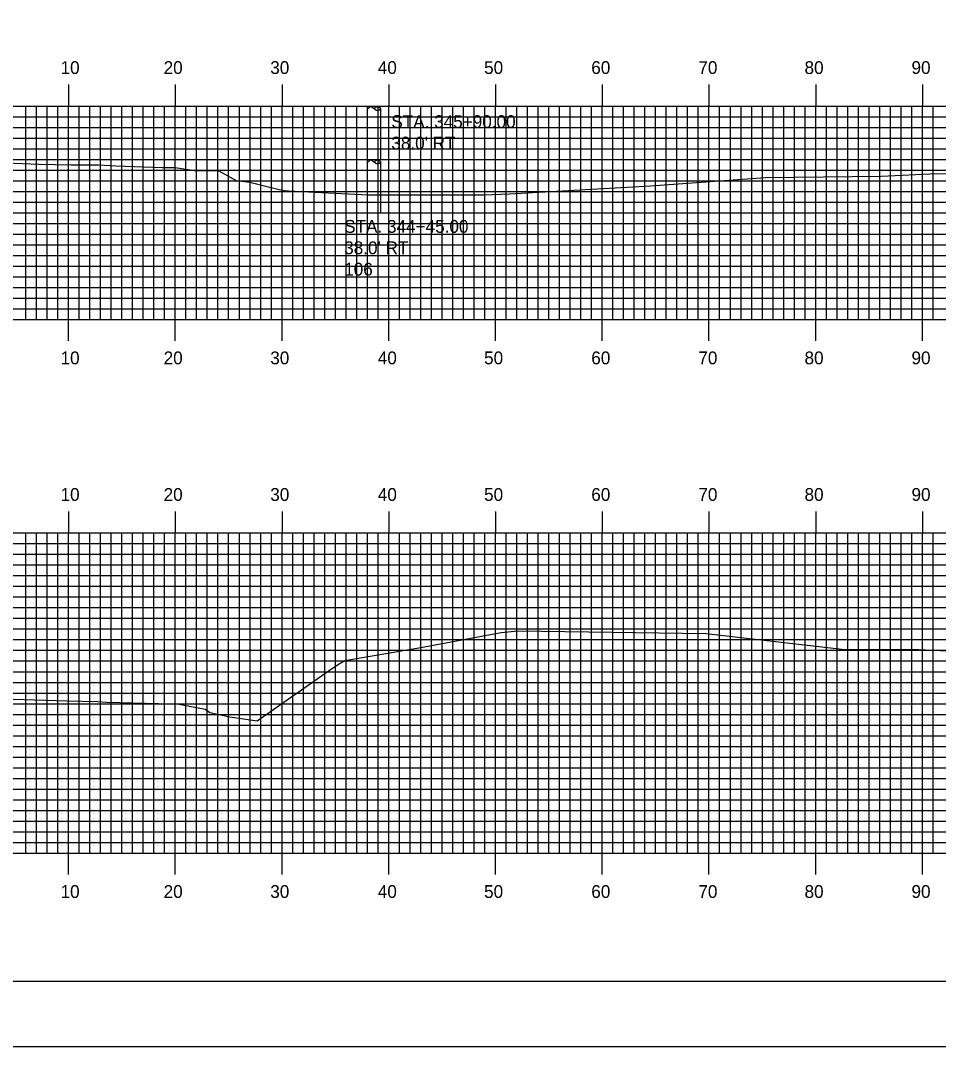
# Model space of a CAD drawing. Extents: x 1825540 to 1825883, y 442591 to 442811.
# Drawn here: x 1825711.4 to 1825797.4, y 442590.5 to 442686.7 of the extents above; entities that cross this region are included whole.
import ezdxf

# ---------------------------------------------------------------- set-up
doc = ezdxf.new("R2010")
doc.units = 0
for name, color, linetype in [('BORDER', 7, 'Continuous'), ('D_Drainage_Text', 7, 'Continuous'), ('D_Utilities_Pole_Joint', 7, 'Continuous'), ('H_V ANNOTATION', 7, 'Continuous'), ('MAJOR', 7, 'Continuous'), ('MINOR', 7, 'Continuous'), ('PLOT BOUNDARY', 7, 'Continuous'), ('S_Roadway_Centerline', 7, 'Continuous')]:
    doc.layers.add(name, color=color, linetype=linetype)

msp = doc.modelspace()

# ---------------------------------------------------------------- linework, layer by layer
at = {"layer": 'BORDER'}
msp.add_lwpolyline([(1825556.274, 442596.665), (1825876.274, 442596.665), (1825876.274, 442806.665), (1825556.274, 442806.665)], close=True, dxfattribs=at)
at = {"layer": 'D_Utilities_Pole_Joint'}
for p, q in [((1825743.874, 442678.423), (1825744.03, 442678.533)), ((1825743.874, 442673.665), (1825743.874, 442678.423)), ((1825744.343, 442678.533), (1825744.499, 442678.423)), ((1825744.655, 442678.533), (1825744.499, 442678.423)), ((1825744.499, 442678.423), (1825744.655, 442678.312)), ((1825745.124, 442678.423), (1825744.968, 442678.533)), ((1825744.968, 442678.312), (1825745.124, 442678.423)), ((1825745.124, 442673.665), (1825745.124, 442678.423)), ((1825743.874, 442673.423), (1825744.03, 442673.533)), ((1825743.874, 442668.665), (1825743.874, 442673.423)), ((1825744.343, 442673.533), (1825744.499, 442673.423)), ((1825744.655, 442673.533), (1825744.499, 442673.423)), ((1825744.499, 442673.423), (1825744.655, 442673.312)), ((1825745.124, 442673.423), (1825744.968, 442673.533)), ((1825744.968, 442673.312), (1825745.124, 442673.423)), ((1825745.124, 442668.665), (1825745.124, 442673.423))]:
    msp.add_line(p, q, dxfattribs=at)
for centre, start, end in [((1825744.187, 442678.312), 90, 125.26439), ((1825744.187, 442678.312), 54.73561, 90), ((1825744.812, 442678.312), 90, 125.26439), ((1825744.812, 442678.533), 234.73561, 270), ((1825744.812, 442678.312), 54.73561, 90), ((1825744.812, 442678.533), 270, 305.26439), ((1825744.187, 442673.312), 90, 125.26439), ((1825744.187, 442673.312), 54.73561, 90), ((1825744.812, 442673.312), 90, 125.26439), ((1825744.812, 442673.312), 54.73561, 90), ((1825744.812, 442673.533), 234.73561, 270), ((1825744.812, 442673.533), 270, 305.26439)]:
    msp.add_arc(centre, 0.271, start, end, dxfattribs=at)
at = {"layer": 'MAJOR'}
for p, q in [((1825715.874, 442680.669), (1825715.874, 442678.665)), ((1825725.874, 442680.669), (1825725.874, 442678.665)), ((1825735.874, 442680.669), (1825735.874, 442678.665)), ((1825745.874, 442680.669), (1825745.874, 442678.665)), ((1825755.874, 442680.669), (1825755.874, 442678.665)), ((1825765.874, 442680.669), (1825765.874, 442678.665)), ((1825775.874, 442680.669), (1825775.874, 442678.665)), ((1825785.874, 442680.669), (1825785.874, 442678.665)), ((1825795.874, 442680.669), (1825795.874, 442678.665)), ((1825565.874, 442678.665), (1825845.874, 442678.665)), ((1825565.874, 442678.665), (1825845.874, 442678.665)), ((1825715.874, 442658.665), (1825715.874, 442678.665)), ((1825725.874, 442658.665), (1825725.874, 442678.665)), ((1825735.874, 442658.665), (1825735.874, 442678.665)), ((1825745.874, 442658.665), (1825745.874, 442678.665)), ((1825755.874, 442658.665), (1825755.874, 442678.665)), ((1825765.874, 442658.665), (1825765.874, 442678.665)), ((1825775.874, 442658.665), (1825775.874, 442678.665)), ((1825785.874, 442658.665), (1825785.874, 442678.665)), ((1825795.874, 442658.665), (1825795.874, 442678.665)), ((1825565.874, 442673.665), (1825845.874, 442673.665)), ((1825565.874, 442668.665), (1825845.874, 442668.665)), ((1825565.874, 442663.665), (1825845.874, 442663.665)), ((1825565.874, 442658.665), (1825845.874, 442658.665)), ((1825565.874, 442658.665), (1825845.874, 442658.665)), ((1825715.874, 442656.661), (1825715.874, 442658.665)), ((1825725.874, 442656.661), (1825725.874, 442658.665)), ((1825735.874, 442656.661), (1825735.874, 442658.665)), ((1825745.874, 442656.661), (1825745.874, 442658.665)), ((1825755.874, 442656.661), (1825755.874, 442658.665)), ((1825765.874, 442656.661), (1825765.874, 442658.665)), ((1825775.874, 442656.661), (1825775.874, 442658.665)), ((1825785.874, 442656.661), (1825785.874, 442658.665)), ((1825795.874, 442656.661), (1825795.874, 442658.665)), ((1825715.874, 442640.669), (1825715.874, 442638.665)), ((1825725.874, 442640.669), (1825725.874, 442638.665)), ((1825735.874, 442640.669), (1825735.874, 442638.665)), ((1825745.874, 442640.669), (1825745.874, 442638.665)), ((1825755.874, 442640.669), (1825755.874, 442638.665)), ((1825765.874, 442640.669), (1825765.874, 442638.665)), ((1825775.874, 442640.669), (1825775.874, 442638.665)), ((1825785.874, 442640.669), (1825785.874, 442638.665)), ((1825795.874, 442640.669), (1825795.874, 442638.665)), ((1825565.874, 442638.665), (1825845.874, 442638.665)), ((1825565.874, 442638.665), (1825845.874, 442638.665)), ((1825715.874, 442608.665), (1825715.874, 442638.665)), ((1825725.874, 442608.665), (1825725.874, 442638.665)), ((1825735.874, 442608.665), (1825735.874, 442638.665)), ((1825745.874, 442608.665), (1825745.874, 442638.665)), ((1825755.874, 442608.665), (1825755.874, 442638.665)), ((1825765.874, 442608.665), (1825765.874, 442638.665)), ((1825775.874, 442608.665), (1825775.874, 442638.665)), ((1825785.874, 442608.665), (1825785.874, 442638.665)), ((1825795.874, 442608.665), (1825795.874, 442638.665)), ((1825565.874, 442633.665), (1825845.874, 442633.665)), ((1825565.874, 442628.665), (1825845.874, 442628.665)), ((1825565.874, 442623.665), (1825845.874, 442623.665)), ((1825565.874, 442618.665), (1825845.874, 442618.665)), ((1825565.874, 442613.665), (1825845.874, 442613.665)), ((1825565.874, 442608.665), (1825845.874, 442608.665)), ((1825565.874, 442608.665), (1825845.874, 442608.665)), ((1825715.874, 442606.661), (1825715.874, 442608.665)), ((1825725.874, 442606.661), (1825725.874, 442608.665)), ((1825735.874, 442606.661), (1825735.874, 442608.665)), ((1825745.874, 442606.661), (1825745.874, 442608.665)), ((1825755.874, 442606.661), (1825755.874, 442608.665)), ((1825765.874, 442606.661), (1825765.874, 442608.665)), ((1825775.874, 442606.661), (1825775.874, 442608.665)), ((1825785.874, 442606.661), (1825785.874, 442608.665)), ((1825795.874, 442606.661), (1825795.874, 442608.665))]:
    msp.add_line(p, q, dxfattribs=at)
at = {"layer": 'MINOR'}
for p, q in [((1825711.874, 442658.665), (1825711.874, 442678.665)), ((1825712.874, 442658.665), (1825712.874, 442678.665)), ((1825713.874, 442658.665), (1825713.874, 442678.665)), ((1825714.874, 442658.665), (1825714.874, 442678.665)), ((1825716.874, 442658.665), (1825716.874, 442678.665)), ((1825717.874, 442658.665), (1825717.874, 442678.665)), ((1825718.874, 442658.665), (1825718.874, 442678.665)), ((1825719.874, 442658.665), (1825719.874, 442678.665)), ((1825720.874, 442658.665), (1825720.874, 442678.665)), ((1825721.874, 442658.665), (1825721.874, 442678.665)), ((1825722.874, 442658.665), (1825722.874, 442678.665)), ((1825723.874, 442658.665), (1825723.874, 442678.665)), ((1825724.874, 442658.665), (1825724.874, 442678.665)), ((1825726.874, 442658.665), (1825726.874, 442678.665)), ((1825727.874, 442658.665), (1825727.874, 442678.665)), ((1825728.874, 442658.665), (1825728.874, 442678.665)), ((1825729.874, 442658.665), (1825729.874, 442678.665)), ((1825730.874, 442658.665), (1825730.874, 442678.665)), ((1825731.874, 442658.665), (1825731.874, 442678.665)), ((1825732.874, 442658.665), (1825732.874, 442678.665)), ((1825733.874, 442658.665), (1825733.874, 442678.665)), ((1825734.874, 442658.665), (1825734.874, 442678.665)), ((1825736.874, 442658.665), (1825736.874, 442678.665)), ((1825737.874, 442658.665), (1825737.874, 442678.665)), ((1825738.874, 442658.665), (1825738.874, 442678.665)), ((1825739.874, 442658.665), (1825739.874, 442678.665)), ((1825740.874, 442658.665), (1825740.874, 442678.665)), ((1825741.874, 442658.665), (1825741.874, 442678.665)), ((1825742.874, 442658.665), (1825742.874, 442678.665)), ((1825743.874, 442658.665), (1825743.874, 442678.665)), ((1825744.874, 442658.665), (1825744.874, 442678.665)), ((1825746.874, 442658.665), (1825746.874, 442678.665)), ((1825747.874, 442658.665), (1825747.874, 442678.665)), ((1825748.874, 442658.665), (1825748.874, 442678.665)), ((1825749.874, 442658.665), (1825749.874, 442678.665)), ((1825750.874, 442658.665), (1825750.874, 442678.665)), ((1825751.874, 442658.665), (1825751.874, 442678.665)), ((1825752.874, 442658.665), (1825752.874, 442678.665)), ((1825753.874, 442658.665), (1825753.874, 442678.665)), ((1825754.874, 442658.665), (1825754.874, 442678.665)), ((1825756.874, 442658.665), (1825756.874, 442678.665)), ((1825757.874, 442658.665), (1825757.874, 442678.665)), ((1825758.874, 442658.665), (1825758.874, 442678.665)), ((1825759.874, 442658.665), (1825759.874, 442678.665)), ((1825760.874, 442658.665), (1825760.874, 442678.665)), ((1825761.874, 442658.665), (1825761.874, 442678.665)), ((1825762.874, 442658.665), (1825762.874, 442678.665)), ((1825763.874, 442658.665), (1825763.874, 442678.665)), ((1825764.874, 442658.665), (1825764.874, 442678.665)), ((1825766.874, 442658.665), (1825766.874, 442678.665)), ((1825767.874, 442658.665), (1825767.874, 442678.665)), ((1825768.874, 442658.665), (1825768.874, 442678.665)), ((1825769.874, 442658.665), (1825769.874, 442678.665)), ((1825770.874, 442658.665), (1825770.874, 442678.665)), ((1825771.874, 442658.665), (1825771.874, 442678.665)), ((1825772.874, 442658.665), (1825772.874, 442678.665)), ((1825773.874, 442658.665), (1825773.874, 442678.665)), ((1825774.874, 442658.665), (1825774.874, 442678.665)), ((1825776.874, 442658.665), (1825776.874, 442678.665)), ((1825777.874, 442658.665), (1825777.874, 442678.665)), ((1825778.874, 442658.665), (1825778.874, 442678.665)), ((1825779.874, 442658.665), (1825779.874, 442678.665)), ((1825780.874, 442658.665), (1825780.874, 442678.665)), ((1825781.874, 442658.665), (1825781.874, 442678.665)), ((1825782.874, 442658.665), (1825782.874, 442678.665)), ((1825783.874, 442658.665), (1825783.874, 442678.665)), ((1825784.874, 442658.665), (1825784.874, 442678.665)), ((1825786.874, 442658.665), (1825786.874, 442678.665)), ((1825787.874, 442658.665), (1825787.874, 442678.665)), ((1825788.874, 442658.665), (1825788.874, 442678.665)), ((1825789.874, 442658.665), (1825789.874, 442678.665)), ((1825790.874, 442658.665), (1825790.874, 442678.665)), ((1825791.874, 442658.665), (1825791.874, 442678.665)), ((1825792.874, 442658.665), (1825792.874, 442678.665)), ((1825793.874, 442658.665), (1825793.874, 442678.665)), ((1825794.874, 442658.665), (1825794.874, 442678.665)), ((1825796.874, 442658.665), (1825796.874, 442678.665)), ((1825565.874, 442677.665), (1825845.874, 442677.665)), ((1825565.874, 442676.665), (1825845.874, 442676.665)), ((1825565.874, 442675.665), (1825845.874, 442675.665)), ((1825565.874, 442674.665), (1825845.874, 442674.665)), ((1825565.874, 442672.665), (1825845.874, 442672.665)), ((1825565.874, 442671.665), (1825845.874, 442671.665)), ((1825565.874, 442670.665), (1825845.874, 442670.665)), ((1825565.874, 442669.665), (1825845.874, 442669.665)), ((1825565.874, 442667.665), (1825845.874, 442667.665)), ((1825565.874, 442666.665), (1825845.874, 442666.665)), ((1825565.874, 442665.665), (1825845.874, 442665.665)), ((1825565.874, 442664.665), (1825845.874, 442664.665)), ((1825565.874, 442662.665), (1825845.874, 442662.665)), ((1825565.874, 442661.665), (1825845.874, 442661.665)), ((1825565.874, 442660.665), (1825845.874, 442660.665)), ((1825565.874, 442659.665), (1825845.874, 442659.665)), ((1825711.874, 442608.665), (1825711.874, 442638.665)), ((1825712.874, 442608.665), (1825712.874, 442638.665)), ((1825713.874, 442608.665), (1825713.874, 442638.665)), ((1825714.874, 442608.665), (1825714.874, 442638.665)), ((1825716.874, 442608.665), (1825716.874, 442638.665)), ((1825717.874, 442608.665), (1825717.874, 442638.665)), ((1825718.874, 442608.665), (1825718.874, 442638.665)), ((1825719.874, 442608.665), (1825719.874, 442638.665)), ((1825720.874, 442608.665), (1825720.874, 442638.665)), ((1825721.874, 442608.665), (1825721.874, 442638.665)), ((1825722.874, 442608.665), (1825722.874, 442638.665)), ((1825723.874, 442608.665), (1825723.874, 442638.665)), ((1825724.874, 442608.665), (1825724.874, 442638.665)), ((1825726.874, 442608.665), (1825726.874, 442638.665)), ((1825727.874, 442608.665), (1825727.874, 442638.665)), ((1825728.874, 442608.665), (1825728.874, 442638.665)), ((1825729.874, 442608.665), (1825729.874, 442638.665)), ((1825730.874, 442608.665), (1825730.874, 442638.665)), ((1825731.874, 442608.665), (1825731.874, 442638.665)), ((1825732.874, 442608.665), (1825732.874, 442638.665)), ((1825733.874, 442608.665), (1825733.874, 442638.665)), ((1825734.874, 442608.665), (1825734.874, 442638.665)), ((1825736.874, 442608.665), (1825736.874, 442638.665)), ((1825737.874, 442608.665), (1825737.874, 442638.665)), ((1825738.874, 442608.665), (1825738.874, 442638.665)), ((1825739.874, 442608.665), (1825739.874, 442638.665)), ((1825740.874, 442608.665), (1825740.874, 442638.665)), ((1825741.874, 442608.665), (1825741.874, 442638.665)), ((1825742.874, 442608.665), (1825742.874, 442638.665)), ((1825743.874, 442608.665), (1825743.874, 442638.665)), ((1825744.874, 442608.665), (1825744.874, 442638.665)), ((1825746.874, 442608.665), (1825746.874, 442638.665)), ((1825747.874, 442608.665), (1825747.874, 442638.665)), ((1825748.874, 442608.665), (1825748.874, 442638.665)), ((1825749.874, 442608.665), (1825749.874, 442638.665)), ((1825750.874, 442608.665), (1825750.874, 442638.665)), ((1825751.874, 442608.665), (1825751.874, 442638.665)), ((1825752.874, 442608.665), (1825752.874, 442638.665)), ((1825753.874, 442608.665), (1825753.874, 442638.665)), ((1825754.874, 442608.665), (1825754.874, 442638.665)), ((1825756.874, 442608.665), (1825756.874, 442638.665)), ((1825757.874, 442608.665), (1825757.874, 442638.665)), ((1825758.874, 442608.665), (1825758.874, 442638.665)), ((1825759.874, 442608.665), (1825759.874, 442638.665)), ((1825760.874, 442608.665), (1825760.874, 442638.665)), ((1825761.874, 442608.665), (1825761.874, 442638.665)), ((1825762.874, 442608.665), (1825762.874, 442638.665)), ((1825763.874, 442608.665), (1825763.874, 442638.665)), ((1825764.874, 442608.665), (1825764.874, 442638.665)), ((1825766.874, 442608.665), (1825766.874, 442638.665)), ((1825767.874, 442608.665), (1825767.874, 442638.665)), ((1825768.874, 442608.665), (1825768.874, 442638.665)), ((1825769.874, 442608.665), (1825769.874, 442638.665)), ((1825770.874, 442608.665), (1825770.874, 442638.665)), ((1825771.874, 442608.665), (1825771.874, 442638.665)), ((1825772.874, 442608.665), (1825772.874, 442638.665)), ((1825773.874, 442608.665), (1825773.874, 442638.665)), ((1825774.874, 442608.665), (1825774.874, 442638.665)), ((1825776.874, 442608.665), (1825776.874, 442638.665)), ((1825777.874, 442608.665), (1825777.874, 442638.665)), ((1825778.874, 442608.665), (1825778.874, 442638.665)), ((1825779.874, 442608.665), (1825779.874, 442638.665)), ((1825780.874, 442608.665), (1825780.874, 442638.665)), ((1825781.874, 442608.665), (1825781.874, 442638.665)), ((1825782.874, 442608.665), (1825782.874, 442638.665)), ((1825783.874, 442608.665), (1825783.874, 442638.665)), ((1825784.874, 442608.665), (1825784.874, 442638.665)), ((1825786.874, 442608.665), (1825786.874, 442638.665)), ((1825787.874, 442608.665), (1825787.874, 442638.665)), ((1825788.874, 442608.665), (1825788.874, 442638.665)), ((1825789.874, 442608.665), (1825789.874, 442638.665)), ((1825790.874, 442608.665), (1825790.874, 442638.665)), ((1825791.874, 442608.665), (1825791.874, 442638.665)), ((1825792.874, 442608.665), (1825792.874, 442638.665)), ((1825793.874, 442608.665), (1825793.874, 442638.665)), ((1825794.874, 442608.665), (1825794.874, 442638.665)), ((1825796.874, 442608.665), (1825796.874, 442638.665)), ((1825565.874, 442637.665), (1825845.874, 442637.665)), ((1825565.874, 442636.665), (1825845.874, 442636.665)), ((1825565.874, 442635.665), (1825845.874, 442635.665)), ((1825565.874, 442634.665), (1825845.874, 442634.665)), ((1825565.874, 442632.665), (1825845.874, 442632.665)), ((1825565.874, 442631.665), (1825845.874, 442631.665)), ((1825565.874, 442630.665), (1825845.874, 442630.665)), ((1825565.874, 442629.665), (1825845.874, 442629.665)), ((1825565.874, 442627.665), (1825845.874, 442627.665)), ((1825565.874, 442626.665), (1825845.874, 442626.665)), ((1825565.874, 442625.665), (1825845.874, 442625.665)), ((1825565.874, 442624.665), (1825845.874, 442624.665)), ((1825565.874, 442622.665), (1825845.874, 442622.665)), ((1825565.874, 442621.665), (1825845.874, 442621.665)), ((1825565.874, 442620.665), (1825845.874, 442620.665)), ((1825565.874, 442619.665), (1825845.874, 442619.665)), ((1825565.874, 442617.665), (1825845.874, 442617.665)), ((1825565.874, 442616.665), (1825845.874, 442616.665)), ((1825565.874, 442615.665), (1825845.874, 442615.665)), ((1825565.874, 442614.665), (1825845.874, 442614.665)), ((1825565.874, 442612.665), (1825845.874, 442612.665)), ((1825565.874, 442611.665), (1825845.874, 442611.665)), ((1825565.874, 442610.665), (1825845.874, 442610.665)), ((1825565.874, 442609.665), (1825845.874, 442609.665))]:
    msp.add_line(p, q, dxfattribs=at)
at = {"layer": 'PLOT BOUNDARY'}
msp.add_lwpolyline([(1825540.087, 442590.547), (1825880.087, 442590.547), (1825880.087, 442810.547), (1825540.087, 442810.547)], close=True, dxfattribs=at)
msp.add_lwpolyline([(1825540.087, 442590.547), (1825880.087, 442590.547), (1825880.087, 442810.547), (1825540.087, 442810.547)], close=True, dxfattribs=at)
at = {"layer": 'S_Roadway_Centerline'}
for points in [[(1825709.987, 442673.349), (1825713.123, 442673.21), (1825716.119, 442673.149), (1825718.687, 442673.155), (1825720.317, 442673.05), (1825724.647, 442672.903), (1825725.865, 442672.912), (1825727.687, 442672.622), (1825729.959, 442672.593), (1825731.582, 442671.681), (1825732.845, 442671.52), (1825735.619, 442670.844), (1825735.959, 442670.771), (1825736.297, 442670.708), (1825736.475, 442670.709), (1825743.935, 442670.35), (1825754.427, 442670.341), (1825754.763, 442670.342), (1825757.2, 442670.449), (1825770.379, 442671.174), (1825781.156, 442671.959), (1825791.996, 442672.081), (1825797.221, 442672.353), (1825800.871, 442672.29)], [(1825706.637, 442623.226), (1825715.7, 442622.926), (1825718.565, 442622.868), (1825718.624, 442622.855), (1825719.475, 442622.798), (1825725.514, 442622.644), (1825725.935, 442622.67), (1825726.403, 442622.587), (1825728.662, 442622.16), (1825729.111, 442621.827), (1825730.972, 442621.442), (1825733.551, 442621.053), (1825740.199, 442625.702), (1825741.057, 442626.312), (1825741.752, 442626.725), (1825748.887, 442627.937), (1825756.401, 442629.328), (1825757.961, 442629.483), (1825775.619, 442629.236), (1825788.588, 442627.756), (1825794.838, 442627.759), (1825808.349, 442627.133)]]:
    msp.add_lwpolyline(points, dxfattribs=at)

# ---------------------------------------------------------------- texts
at = {"layer": 'D_Drainage_Text'}
for s, p in [('STA. 345+90.00', (1825746.114, 442676.599)), ("38.0' RT", (1825746.114, 442674.595)), ('STA. 344+45.00', (1825741.698, 442666.784)), ("38.0' RT", (1825741.698, 442664.78)), ('106', (1825741.698, 442662.776))]:
    msp.add_text(s, height=1.2, dxfattribs=at).set_placement(p)
at = {"layer": 'H_V ANNOTATION'}
for s, p in [('10', (1825715.125, 442681.665)), ('20', (1825724.782, 442681.665)), ('30', (1825734.771, 442681.665)), ('40', (1825744.846, 442681.665)), ('50', (1825754.803, 442681.665)), ('60', (1825764.846, 442681.665)), ('70', (1825774.878, 442681.665)), ('80', (1825784.825, 442681.665)), ('90', (1825794.846, 442681.665)), ('10', (1825715.125, 442654.465)), ('20', (1825724.782, 442654.465)), ('30', (1825734.771, 442654.465)), ('40', (1825744.846, 442654.465)), ('50', (1825754.803, 442654.465)), ('60', (1825764.846, 442654.465)), ('70', (1825774.878, 442654.465)), ('80', (1825784.825, 442654.465)), ('90', (1825794.846, 442654.465)), ('10', (1825715.125, 442641.665)), ('20', (1825724.782, 442641.665)), ('30', (1825734.771, 442641.665)), ('40', (1825744.846, 442641.665)), ('50', (1825754.803, 442641.665)), ('60', (1825764.846, 442641.665)), ('70', (1825774.878, 442641.665)), ('80', (1825784.825, 442641.665)), ('90', (1825794.846, 442641.665)), ('10', (1825715.125, 442604.465)), ('20', (1825724.782, 442604.465)), ('30', (1825734.771, 442604.465)), ('40', (1825744.846, 442604.465)), ('50', (1825754.803, 442604.465)), ('60', (1825764.846, 442604.465)), ('70', (1825774.878, 442604.465)), ('80', (1825784.825, 442604.465)), ('90', (1825794.846, 442604.465))]:
    msp.add_text(s, height=1.2, dxfattribs=at).set_placement(p)

doc.saveas('drawing.dxf')
